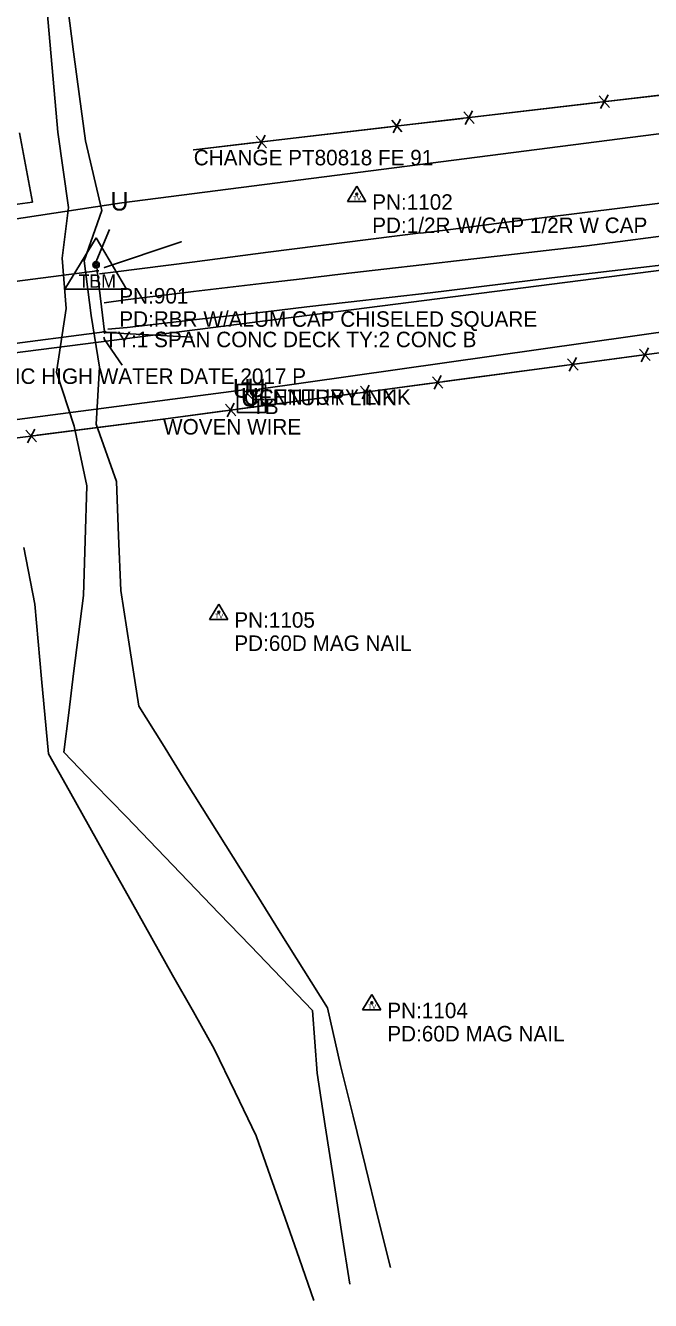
# Model space of a CAD drawing. Extents: x 1568433 to 1572450, y 731863 to 733450.
# Drawn here: x 1570549.4 to 1570751.1, y 731932.2 to 732343.4 of the extents above; entities that cross this region are included whole.
import ezdxf

# ---------------------------------------------------------------- set-up
doc = ezdxf.new("R2010")
doc.units = 0
for name, color, linetype in [('Default', 7, 'Continuous'), ('S_BASELINE', 7, 'Continuous'), ('S_BRIDGE', 7, 'Continuous'), ('S_BRIDGE_ANNOT', 7, 'Continuous'), ('S_EDGE_PAVEMENT', 7, 'Continuous'), ('S_FENCE', 7, 'Continuous'), ('S_FENCE_ANNOT', 7, 'Continuous'), ('S_GUARDRAIL', 7, 'Continuous'), ('S_MSC_PT_SYM', 7, 'Continuous'), ('S_PAVEMENT_CROWN', 7, 'Continuous'), ('S_PRIMARY_CTL', 7, 'Continuous'), ('S_PRIMARY_CTL_ANNOT', 7, 'Continuous'), ('S_RDW_PT_SYM', 7, 'Continuous'), ('S_SECONDARY_CTL', 7, 'Continuous'), ('S_SECONDARY_CTL_ANNOT', 7, 'Continuous'), ('S_STR_PT_SYM', 7, 'Continuous'), ('S_STREAM', 7, 'Continuous'), ('S_SURVEY_TEXT_ANNOT', 7, 'Continuous'), ('S_TELEPHONE_UTILITIES', 7, 'Continuous'), ('S_TELEPHONE_UTILITIES_ANNOT', 7, 'Continuous'), ('S_UNDERGROUND_CABLE', 7, 'Continuous'), ('S_UNDERGROUND_CABLE_ANNOT', 7, 'Continuous'), ('S_WALL', 7, 'Continuous')]:
    doc.layers.add(name, color=color, linetype=linetype)

msp = doc.modelspace()

# ---------------------------------------------------------------- linework, layer by layer
at = {"layer": 'S_BASELINE'}
msp.add_line((1570488.07, 732230.45), (1571317.07, 732336.49), dxfattribs=at)
at = {"layer": 'S_BRIDGE'}
for p, q in [((1570522.49, 732257.91), (1570572.6, 732264.24)), ((1570572.6, 732264.24), (1570574.94, 732244.65)), ((1570574.94, 732244.65), (1570524.95, 732238.13))]:
    msp.add_line(p, q, dxfattribs=at)
at = {"layer": 'S_EDGE_PAVEMENT'}
for points in [[(1570573.25, 732263.31), (1570578.58, 732264.01), (1570603.18, 732267.13), (1570627.78, 732270.25), (1570652.38, 732273.37), (1570676.98, 732276.49), (1570677.02, 732276.46), (1570690.04, 732278.09), (1570703.06, 732279.72), (1570716.07, 732281.35), (1570729.09, 732282.97), (1570742.1, 732284.58), (1570755.11, 732286.19)], [(1570575.94, 732245.46), (1570582.24, 732245.98), (1570604.61, 732248.54), (1570626.99, 732251.11), (1570640.25, 732252.63), (1570653.52, 732254.15), (1570666.79, 732255.67), (1570680.05, 732257.19), (1570693.11, 732258.79), (1570706.17, 732260.38), (1570719.23, 732261.98), (1570732.28, 732263.58), (1570745.24, 732265.07), (1570758.2, 732266.55)]]:
    msp.add_lwpolyline(points, dxfattribs=at)
at = {"layer": 'S_FENCE'}
for p, q in [((1570603.72, 732303.31), (1570885.13, 732336.24)), ((1570734.56, 732320.68), (1570737.88, 732316.95)), ((1570734.56, 732320.68), (1570737.88, 732316.95)), ((1570735.04, 732316.61), (1570737.41, 732321.02)), ((1570735.04, 732316.61), (1570737.41, 732321.02)), ((1570690.87, 732315.57), (1570694.19, 732311.83)), ((1570690.87, 732315.57), (1570694.19, 732311.83)), ((1570691.35, 732311.5), (1570693.72, 732315.9)), ((1570691.35, 732311.5), (1570693.72, 732315.9)), ((1570667.6, 732312.85), (1570670.92, 732309.11)), ((1570667.6, 732312.85), (1570670.92, 732309.11)), ((1570668.08, 732308.78), (1570670.45, 732313.18)), ((1570668.08, 732308.78), (1570670.45, 732313.18)), ((1570623.91, 732307.73), (1570627.23, 732304)), ((1570623.91, 732307.73), (1570627.23, 732304)), ((1570624.38, 732303.66), (1570626.75, 732308.07)), ((1570624.38, 732303.66), (1570626.75, 732308.07)), ((1570593.81, 732216.49), (1570888.4, 732255.74)), ((1570747.6, 732239.04), (1570750.98, 732235.36)), ((1570747.6, 732239.04), (1570750.98, 732235.36)), ((1570748.14, 732234.98), (1570750.44, 732239.42)), ((1570748.14, 732234.98), (1570750.44, 732239.42)), ((1570724.37, 732235.95), (1570727.76, 732232.27)), ((1570724.37, 732235.95), (1570727.76, 732232.27)), ((1570724.91, 732231.89), (1570727.21, 732236.33)), ((1570724.91, 732231.89), (1570727.21, 732236.33)), ((1570680.76, 732230.14), (1570684.14, 732226.46)), ((1570680.76, 732230.14), (1570684.14, 732226.46)), ((1570681.3, 732226.08), (1570683.6, 732230.52)), ((1570681.3, 732226.08), (1570683.6, 732230.52)), ((1570657.53, 732227.04), (1570660.92, 732223.36)), ((1570657.53, 732227.04), (1570660.92, 732223.36)), ((1570658.07, 732222.98), (1570660.37, 732227.42)), ((1570658.07, 732222.98), (1570660.37, 732227.42)), ((1570613.92, 732221.23), (1570617.3, 732217.55)), ((1570613.92, 732221.23), (1570617.3, 732217.55)), ((1570614.46, 732217.17), (1570616.76, 732221.61)), ((1570614.46, 732217.17), (1570616.76, 732221.61)), ((1570462.54, 732199.63), (1570593.81, 732216.49)), ((1570549.56, 732212.87), (1570552.93, 732209.17)), ((1570549.56, 732212.87), (1570552.93, 732209.17)), ((1570550.09, 732208.81), (1570552.41, 732213.23)), ((1570550.09, 732208.81), (1570552.41, 732213.23))]:
    msp.add_line(p, q, dxfattribs=at)
for points in [[(1570737.65, 732318.98), (1570757.51, 732321.31)], [(1570737.65, 732318.98), (1570757.51, 732321.31)], [(1570694.52, 732313.93), (1570734.24, 732318.58)], [(1570694.52, 732313.93), (1570734.24, 732318.58)], [(1570670.68, 732311.15), (1570690.54, 732313.47)], [(1570670.68, 732311.15), (1570690.54, 732313.47)], [(1570627.55, 732306.1), (1570667.27, 732310.75)], [(1570627.55, 732306.1), (1570667.27, 732310.75)], [(1570603.72, 732303.31), (1570623.58, 732305.63)], [(1570603.72, 732303.31), (1570623.58, 732305.63)], [(1570684.43, 732228.56), (1570724.08, 732233.84)], [(1570684.43, 732228.56), (1570724.08, 732233.84)], [(1570727.49, 732234.3), (1570747.31, 732236.94)], [(1570727.49, 732234.3), (1570747.31, 732236.94)], [(1570617.59, 732219.66), (1570657.24, 732224.94)], [(1570617.59, 732219.66), (1570657.24, 732224.94)], [(1570660.65, 732225.39), (1570680.47, 732228.03)], [(1570660.65, 732225.39), (1570680.47, 732228.03)], [(1570593.81, 732216.49), (1570613.63, 732219.13)], [(1570593.81, 732216.49), (1570613.63, 732219.13)], [(1570553.23, 732211.28), (1570592.9, 732216.37)], [(1570553.23, 732211.28), (1570592.9, 732216.37)]]:
    msp.add_lwpolyline(points, dxfattribs=at)
at = {"layer": 'S_GUARDRAIL'}
for p, q in [((1570599.61, 732273.64), (1570574.95, 732265.31)), ((1570603.12, 732242.87), (1570577.2, 732244.26))]:
    msp.add_line(p, q, dxfattribs=at)
at = {"layer": 'S_MSC_PT_SYM'}
for points in [[(1570603.72, 732303.31), (1570603.72, 732303.36), (1570603.72, 732303.31), (1570603.67, 732303.31), (1570603.72, 732303.31), (1570603.72, 732303.26), (1570603.72, 732303.31), (1570603.77, 732303.31)], [(1570593.81, 732216.49), (1570593.81, 732216.54), (1570593.81, 732216.49), (1570593.76, 732216.49), (1570593.81, 732216.49), (1570593.81, 732216.44), (1570593.81, 732216.49), (1570593.86, 732216.49)]]:
    msp.add_lwpolyline(points, dxfattribs=at)
at = {"layer": 'S_PAVEMENT_CROWN'}
msp.add_lwpolyline([(1570574.76, 732254.01), (1570581.64, 732254.94), (1570603.59, 732257.58), (1570625.54, 732260.22), (1570638.72, 732261.75), (1570651.9, 732263.28), (1570665.07, 732264.81), (1570678.25, 732266.34), (1570691.33, 732267.85), (1570704.41, 732269.35), (1570717.49, 732270.86), (1570730.58, 732272.37), (1570743.76, 732274.07), (1570756.94, 732275.76)], dxfattribs=at)
at = {"layer": 'S_PRIMARY_CTL'}
for p, q in [((1570572.19, 732274.93), (1570562.15, 732258.42)), ((1570572.19, 732274.93), (1570562.15, 732258.42)), ((1570572.19, 732274.93), (1570582.01, 732258.42)), ((1570572.19, 732274.93), (1570582.01, 732258.42)), ((1570562.15, 732258.42), (1570582.01, 732258.42)), ((1570562.15, 732258.42), (1570582.01, 732258.42))]:
    msp.add_line(p, q, dxfattribs=at)
for radius in [1.04, 1.04, 0.609, 0.609, 0.344, 0.344]:
    msp.add_circle((1570572.19, 732266.23), radius, dxfattribs=at)
at = {"layer": 'S_RDW_PT_SYM'}
for points in [[(1570599.61, 732273.64), (1570599.61, 732273.69), (1570599.61, 732273.64), (1570599.56, 732273.64), (1570599.61, 732273.64), (1570599.61, 732273.59), (1570599.61, 732273.64), (1570599.67, 732273.64)], [(1570574.95, 732265.31), (1570574.95, 732265.36), (1570574.95, 732265.31), (1570574.9, 732265.31), (1570574.95, 732265.31), (1570574.95, 732265.26), (1570574.95, 732265.31), (1570575, 732265.31)], [(1570577.2, 732244.26), (1570577.2, 732244.31), (1570577.2, 732244.26), (1570577.15, 732244.26), (1570577.2, 732244.26), (1570577.2, 732244.21), (1570577.2, 732244.26), (1570577.25, 732244.26)], [(1570603.12, 732242.87), (1570603.12, 732242.92), (1570603.12, 732242.87), (1570603.07, 732242.87), (1570603.12, 732242.87), (1570603.12, 732242.82), (1570603.12, 732242.87), (1570603.17, 732242.87)]]:
    msp.add_lwpolyline(points, dxfattribs=at)
at = {"layer": 'S_SECONDARY_CTL'}
for p, q in [((1570656.3, 732291.59), (1570653.29, 732286.64)), ((1570656.3, 732291.59), (1570659.25, 732286.64)), ((1570653.29, 732286.64), (1570659.25, 732286.64)), ((1570611.8, 732156.79), (1570608.79, 732151.84)), ((1570611.8, 732156.79), (1570614.75, 732151.84)), ((1570608.79, 732151.84), (1570614.75, 732151.84)), ((1570661.17, 732030.83), (1570658.16, 732025.88)), ((1570661.17, 732030.83), (1570664.12, 732025.88)), ((1570658.16, 732025.88), (1570664.12, 732025.88))]:
    msp.add_line(p, q, dxfattribs=at)
for centre, radius in [((1570656.3, 732288.98), 0.311), ((1570656.3, 732288.98), 0.183), ((1570656.3, 732288.98), 0.103), ((1570611.8, 732154.18), 0.311), ((1570611.8, 732154.18), 0.183), ((1570611.8, 732154.18), 0.103), ((1570661.17, 732028.22), 0.311), ((1570661.17, 732028.22), 0.183), ((1570661.17, 732028.22), 0.103)]:
    msp.add_circle(centre, radius, dxfattribs=at)
at = {"layer": 'S_STR_PT_SYM'}
for points in [[(1570572.6, 732264.24), (1570572.6, 732264.74), (1570572.6, 732264.24), (1570572.1, 732264.24), (1570572.6, 732264.24), (1570572.6, 732263.74), (1570572.6, 732264.24), (1570573.1, 732264.24)], [(1570574.94, 732244.65), (1570574.94, 732245.15), (1570574.94, 732244.65), (1570574.44, 732244.65), (1570574.94, 732244.65), (1570574.94, 732244.15), (1570574.94, 732244.65), (1570575.44, 732244.65)]]:
    msp.add_lwpolyline(points, dxfattribs=at)
at = {"layer": 'S_STREAM'}
for points in [[(1570654.08, 731937.41), (1570651.45, 731954.43), (1570648.82, 731971.44), (1570646.18, 731988.45), (1570643.55, 732005.47), (1570642.09, 732025.67), (1570632.05, 732036.1), (1570622.01, 732046.52), (1570611.97, 732056.95), (1570601.93, 732067.38), (1570591.9, 732077.8), (1570581.86, 732088.23), (1570571.82, 732098.65), (1570561.78, 732109.08), (1570563.36, 732121.71), (1570564.94, 732134.35), (1570566.52, 732146.98), (1570568.1, 732159.61), (1570568.64, 732177.26), (1570569.17, 732194.9), (1570565.1, 732214.13), (1570559.43, 732231.63), (1570562.55, 732252.1), (1570561.29, 732268.36), (1570563.31, 732284.68), (1570559.84, 732309.03), (1570557.68, 732333.41), (1570555.51, 732357.8)], [(1570667.21, 731942.76), (1570663.18, 731959.05), (1570659.15, 731975.34), (1570655.12, 731991.62), (1570651.08, 732007.91), (1570646.88, 732026.53), (1570639.27, 732038.69), (1570631.66, 732050.85), (1570624.04, 732063.02), (1570616.43, 732075.18), (1570608.82, 732087.34), (1570601.21, 732099.51), (1570593.6, 732111.67), (1570585.99, 732123.84), (1570583.06, 732142.51), (1570580.14, 732161.18), (1570579.44, 732178.76), (1570578.74, 732196.34), (1570572.27, 732214.86), (1570573.3, 732233.26), (1570570.64, 732249.85), (1570568.33, 732267.52), (1570574.1, 732283.74), (1570568.73, 732306.26), (1570566.84, 732320.56), (1570564.95, 732334.87), (1570563.05, 732349.18)], [(1570538.62, 732284.67), (1570551.64, 732286.45), (1570551.64, 732286.45), (1570547.43, 732308.84)], [(1570642.51, 731932.16), (1570637.84, 731945.45), (1570633.17, 731958.74), (1570628.51, 731972.03), (1570623.84, 731985.32), (1570617.06, 731999.34), (1570610.28, 732013.36), (1570603.6, 732025.25), (1570596.91, 732037.15), (1570590.23, 732049.04), (1570583.55, 732060.94), (1570576.86, 732072.83), (1570570.18, 732084.73), (1570563.49, 732096.63), (1570556.81, 732108.52), (1570554.61, 732132.65), (1570552.41, 732156.78), (1570548.9, 732175.08)]]:
    msp.add_lwpolyline(points, dxfattribs=at)
at = {"layer": 'S_TELEPHONE_UTILITIES'}
msp.add_lwpolyline([(1570617.83, 732218.57), (1570617.83, 732227.57), (1570626.83, 732227.57), (1570626.83, 732218.57)], close=True, dxfattribs=at)
at = {"layer": 'S_UNDERGROUND_CABLE'}
for p, q in [((1570580.49, 732286.26), (1570886.76, 732325.45)), ((1570429.57, 732263.04), (1570580.49, 732286.26)), ((1570624.71, 732226.07), (1570890.22, 732263.81)), ((1570464.38, 732205.53), (1570619.91, 732225.92)), ((1570619.91, 732225.92), (1570622.56, 732223.08)), ((1570622.56, 732223.08), (1570624.71, 732226.07))]:
    msp.add_line(p, q, dxfattribs=at)
at = {"layer": 'S_WALL'}
for points in [[(1570571.76, 732265.87), (1570571.95, 732266.5), (1570576.56, 732277.62)], [(1570574.66, 732242.84), (1570574.89, 732242.12), (1570580.6, 732233.82)]]:
    msp.add_lwpolyline(points, dxfattribs=at)

# ---------------------------------------------------------------- texts
at = {"layer": 'Default'}
for p in [(1570576.86, 732283.72), (1570616.28, 732223.37), (1570621.08, 732223.52), (1570618.93, 732220.54)]:
    msp.add_text('U', height=6, dxfattribs=at).set_placement(p)
at = {"layer": 'S_BRIDGE_ANNOT'}
msp.add_text('TY:1 SPAN CONC DECK TY:2 CONC B', height=5, dxfattribs=at).set_placement((1570574.94, 732239.65))
at = {"layer": 'S_FENCE_ANNOT'}
for s, p in [('CHANGE PT80818 FE 91', (1570603.72, 732298.31)), ('WOVEN WIRE', (1570593.81, 732211.49))]:
    msp.add_text(s, height=5, dxfattribs=at).set_placement(p)
at = {"layer": 'S_PRIMARY_CTL'}
msp.add_text('TBM', height=4.287, rotation=360, dxfattribs=at).set_placement((1570566.53, 732258.84))
msp.add_text('TBM', height=4.287, dxfattribs=at).set_placement((1570566.53, 732258.84))
at = {"layer": 'S_PRIMARY_CTL_ANNOT'}
for s, p in [('PN:901', (1570579.69, 732253.73)), ('PD:RBR W/ALUM CAP CHISELED SQUARE ', (1570579.69, 732246.23))]:
    msp.add_text(s, height=5, dxfattribs=at).set_placement(p)
at = {"layer": 'S_SECONDARY_CTL'}
for p in [(1570655.09, 732286.97), (1570610.59, 732152.17), (1570659.97, 732026.21)]:
    msp.add_text('TV', height=1.5, dxfattribs=at).set_placement(p)
at = {"layer": 'S_SECONDARY_CTL_ANNOT'}
for s, p in [('PN:1102', (1570661.3, 732283.98)), ('PD:1/2R W/CAP 1/2R W CAP', (1570661.3, 732276.48)), ('PN:1105', (1570616.8, 732149.18)), ('PD:60D MAG NAIL', (1570616.8, 732141.68)), ('PN:1104', (1570666.17, 732023.22)), ('PD:60D MAG NAIL', (1570666.17, 732015.72))]:
    msp.add_text(s, height=5, dxfattribs=at).set_placement(p)
at = {"layer": 'S_SURVEY_TEXT_ANNOT'}
msp.add_text('HISTORIC HIGH WATER DATE 2017 P', height=5, dxfattribs=at).set_placement((1570520.69, 732227.8))
at = {"layer": 'S_TELEPHONE_UTILITIES'}
msp.add_text('T', height=6, dxfattribs=at).set_placement((1570620.39, 732220.07))
at = {"layer": 'S_TELEPHONE_UTILITIES_ANNOT'}
msp.add_text('TB', height=5, dxfattribs=at).set_placement((1570622.56, 732218.08))
at = {"layer": 'S_UNDERGROUND_CABLE_ANNOT'}
for s, p in [('CENTURY LINK', (1570619.91, 732220.92)), ('CENTURY LINK', (1570624.71, 732221.07)), ('TB', (1570622.56, 732218.08))]:
    msp.add_text(s, height=5, dxfattribs=at).set_placement(p)

doc.saveas('drawing.dxf')
